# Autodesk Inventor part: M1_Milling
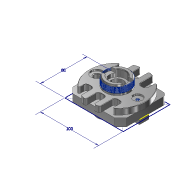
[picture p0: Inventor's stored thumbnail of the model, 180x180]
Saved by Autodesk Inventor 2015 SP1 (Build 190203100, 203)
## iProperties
Created: 2015-04
Part Number: M1_Milling
Material: Alumínio 6061
Document SubType Name: Modeling
Designer: Andrew Almeida
Density: 2.7 g/cm^3
Appearance: Alumínio - Plano
Title: C:/Users/Andrew Almeida/Documents/Projeto WS2015/WS2015 CAD Data ANLAS/07/#07 - CNC Milling/01 - 3D Models/M1_Milling.stp
Creation Date: 2015-04-23
Sending System: Autodesk Translation Framework v4.0.0.5211
Preprocessor: ST-DEVELOPER v16.1
Author: Andrew Almeida
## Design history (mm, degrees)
node "M1_Milling1"
feature "Rosca1" dims "d0" = 10, "d1" = 0
sketch "Esboço2"
  geometry: L1 (21, 0)-(21, 10); L2 (21, 10)-(20.259, 10); L3 (20.259, 10)-(20.259, 0); L4 (20.259, 0)-(21, 0); L5 (0, -11.3)-(0, 53.8) reference
  constraints: 8 end point
revolve "Revolução1" sketch "Esboço2" stored, may be unused: angle "d11" = 0 deg
sketch "Esboço3"
  geometry: L1 (21, 0)-(21, 10); L2 (21, 10)-(20.259, 10); L3 (20.259, 10)-(20.259, 0); L4 (20.259, 0)-(21, 0); L5 (0, -11.3)-(0, 53.8) reference
  constraints: 8 end point
revolve "Revolução2" sketch "Esboço3" stored, may be unused: angle "d12" = 0 deg
sketch "Esboço1"
  geometry: L1 (-0.583, -20.309)-(-0.5, -20.309); L2 (0.083, -20.95)-(0, -21.11); L3 (-1, -21.11)-(-1.083, -20.95); L4 (-0.417, -20.309)-(-0.5, -20.149); L5 (-0.5, -20.149)-(-0.583, -20.309); L6 (-1, -21.11)-(-0.917, -20.95); L7 (-0.417, -20.309)-(-0.083, -20.95); L8 (-1.083, -20.95)-(-0.917, -20.95); L9 (0.083, -20.95)-(-0.083, -20.95); L10 (-1, -21.11)-(-1, -20.95); L11 (0, -21.11)-(0, -20.95); L12 (-0.5, -20.149)-(-0.5, -20.259); L13 (-1, -21)-(0, -21); L14 (-0.083, -20.95)-(0, -21.11); L15 (-0.917, -20.95)-(-0.583, -20.309); L16 (0, 0)-(0, 0.018); L17 (0, 0.018)-(0, 0); L18 (0, 0)-(0.033, 0); L19 (-0.5, -20.259)-(-0.5, -20.309); L20 (-0.5, -20.309)-(-0.417, -20.309); A1 r 0.094 centre (-1, -20.906) between (-1.083, -20.95) and (-1, -21); A2 r 0.094 centre (-1, -20.906) between (-1, -21) and (-0.917, -20.95); A3 r 0.094 centre (0, -20.906) between (-0.083, -20.95) and (0, -21); A4 r 0.094 centre (0, -20.906) between (0, -21) and (0.083, -20.95); A5 r 0.094 centre (-0.5, -20.353) between (-0.5, -20.259) and (-0.583, -20.309); A6 r 0.094 centre (-0.5, -20.353) between (-0.417, -20.309) and (-0.5, -20.259)
  constraints: 40 end point, 12 point on circle, 10 parallel, 8 tangent, 6 centre point, 6 collinear, 2 midpoint, 2 point on line, 1 horizontal, 1 perpendicular, 3 other
  dimensions: "d2" = 55 deg angle of L7 L15 (= d9); "d3" = 0.16008 distance of L4.end L1.end (= 0.160083 x Esboço1_Pitch); "d4" = 0.16008 distance of L2.end L11.end (= 0.160083 x Esboço1_Pitch); "Esboço1_ThreadOffset" = 0 distance between parallel lines of L16 L11; "Esboço1_MajorRadius" = 21 distance from line of L13 L16.start; "d7" = 1 distance from line of L2.end L10 (= Esboço1_Pitch); "Esboço1_MinorRadius" = 20.25854 distance edge to line of A6 L18 (derived)
feature "Espiral1" sketch "Esboço1" pitch "d13" = 1.5015; turns "d15" = 1; dims "d14" = 13, "d16" = 0, angle "d17" = 0 deg, angle "d18" = 0 deg, "d19" = 0, "d20" = 0
feature "Rosca2" dims "d21" = 10, "d22" = 0
sketch "Esboço5"
  geometry: L1 (2.458, 0)-(2.458, 14.1); L2 (2.458, 14.1)-(1.717, 14.1); L3 (1.717, 14.1)-(1.717, 0); L4 (1.717, 0)-(2.458, 0); L5 (0, -27.3)-(0, 37.8) reference
  constraints: 8 end point
revolve "Revolução3" sketch "Esboço5" stored, may be unused: angle "d32" = 0 deg
sketch "Esboço4"
  geometry: L1 (-0.583, -0.051)-(-0.5, -0.051); L2 (0.083, -0.691)-(0, -0.851); L3 (-1, -0.851)-(-1.083, -0.691); L4 (-0.417, -0.051)-(-0.5, 0.109); L5 (-0.5, 0.109)-(-0.583, -0.051); L6 (-1, -0.851)-(-0.917, -0.691); L7 (-0.417, -0.051)-(-0.083, -0.691); L8 (-1.083, -0.691)-(-0.917, -0.691); L9 (0.083, -0.691)-(-0.083, -0.691); L10 (-1, -0.851)-(-1, -0.691); L11 (0, -0.851)-(0, -0.691); L12 (-0.5, 0.109)-(-0.5, 0); L13 (-1, -0.742)-(0, -0.742); L14 (-0.083, -0.691)-(0, -0.851); L15 (-0.917, -0.691)-(-0.583, -0.051); L16 (0, 0)-(0, 0.018); L17 (0, 0.018)-(0, 0); L18 (0, 0)-(0.033, 0); L19 (-0.5, 0)-(-0.5, -0.051); L20 (-0.5, -0.051)-(-0.417, -0.051); A1 r 0.094 centre (-1, -0.648) between (-1.083, -0.691) and (-1, -0.742); A2 r 0.094 centre (-1, -0.648) between (-1, -0.742) and (-0.917, -0.691); A3 r 0.094 centre (0, -0.648) between (-0.083, -0.691) and (0, -0.742); A4 r 0.094 centre (0, -0.648) between (0, -0.742) and (0.083, -0.691); A5 r 0.094 centre (-0.5, -0.094) between (-0.5, 0) and (-0.583, -0.051); A6 r 0.094 centre (-0.5, -0.094) between (-0.417, -0.051) and (-0.5, 0)
  constraints: 40 end point, 12 point on circle, 10 parallel, 8 tangent, 6 centre point, 6 collinear, 2 midpoint, 2 point on line, 1 horizontal, 1 perpendicular, 3 other
  dimensions: "d23" = 55 deg angle of L7 L15 (= d30); "d24" = 0.16008 distance of L4.end L1.end (= 0.160083 x Esboço4_Pitch); "d25" = 0.16008 distance of L2.end L11.end (= 0.160083 x Esboço4_Pitch); "Esboço4_ThreadOffset" = 0 distance between parallel lines of L16 L11; "Esboço4_MajorRadius" = 0.74146 distance from line of L13 L16.start; "d28" = 1 distance from line of L2.end L10 (= Esboço4_Pitch); "Esboço4_MinorRadius" = 0 distance edge to line of A6 L18 (derived)
feature "Espiral2" sketch "Esboço4" pitch "d33" = 1.001; turns "d35" = 1; dims "d34" = 16.1, "d36" = 0, angle "d37" = 0 deg, angle "d38" = 0 deg, "d39" = 0, "d40" = 0
sketch "Sketch6"
  geometry: L1 (-12, 0)-(88, 0); L2 (88, 0)-(88, -80); L3 (88, -80)-(-12, -80); L4 (-12, -80)-(-12, 0); L5 (-12, 0)-(88, -80); L6 (88, 0)-(-12, -80); L7 (68.5, -23)-(24, -23) reference; L8 (73.5, -51)-(73.5, -28) reference; L9 (24, -23)-(24, -59.5) reference; L10 (53, -59.5)-(53, -56) reference; L11 (58, -51)-(73.5, -51) reference; L12 (-8, -48)-(12, -48) reference; L13 (-8, -32)-(-8, -48) reference; L14 (12, -32)-(-8, -32) reference; L15 (12, -48)-(12, -32) reference; A1 r 5 centre (68.5, -28) between (73.5, -28) and (68.5, -23) reference; A2 r 14.5 centre (38.5, -59.5) between (24, -59.5) and (53, -59.5) reference; A3 r 5 centre (58, -56) between (58, -51) and (53, -56) reference; 1 further point
  constraints: 12 end point, 2 midpoint, 2 parallel, 1 horizontal, 1 perpendicular
  dimensions: "d43" = 100 distance of L2.end L3.end; "d44" = 80 distance of L1.end L2.end
node "Body1"
node "Base1"
node "Sólido2"
node "Sólido3"
other parameters: "d9" = 55 deg [user parameter; used in 1 equation term], "Esboço1_Pitch" = 1 [user parameter; used in 3 equation terms], "d30" = 55 deg [user parameter; used in 1 equation term], "Esboço4_Pitch" = 1 [user parameter; used in 3 equation terms]
